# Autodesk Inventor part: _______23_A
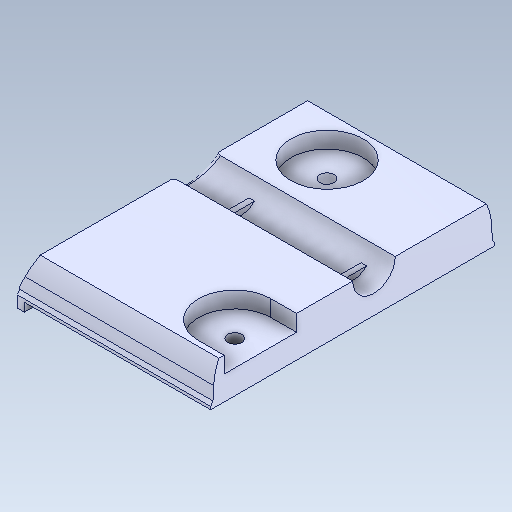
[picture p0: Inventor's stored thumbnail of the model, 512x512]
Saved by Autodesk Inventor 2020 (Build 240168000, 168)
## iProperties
Created: 2017-09
Part Number: _______23_A
Material: Générique
Document SubType Name: Modeling
Designer: bruno
Density: 1 g/cm^3
Appearance: Par défaut
Author: bruno
Sending System: SolidWorks 2016
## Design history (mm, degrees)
feature "Importée1"
node "Solide1"
